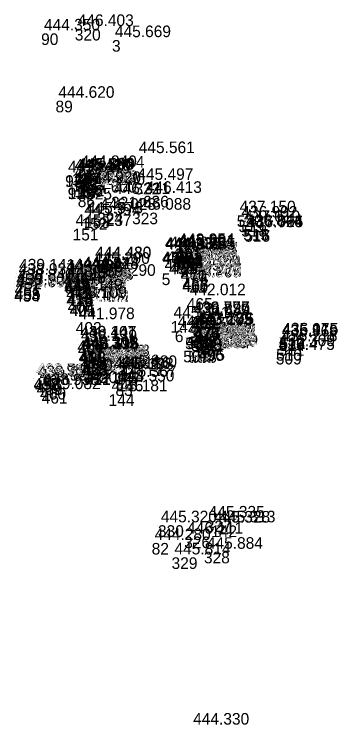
# Model space of a CAD drawing. Extents: x -874038 to -859694, y -1059487 to -1049069.
# Drawn here: x -862371.8 to -862338.4, y -1055776.5 to -1055703.1 of the extents above; entities that cross this region are included whole.
import ezdxf

# ---------------------------------------------------------------- set-up
doc = ezdxf.new("R2010")
doc.units = 0
doc.layers.add('Vrstva 60', color=7, linetype='Continuous')
doc.layers.add('Vrstva 61', color=7, linetype='Continuous')

msp = doc.modelspace()

# ---------------------------------------------------------------- linework, layer by layer
at = {"layer": 'Vrstva 60'}
for p, q in [((-862365.565, -1055704.586), (-862365.565, -1055704.586)), ((-862369.05, -1055705.05), (-862369.05, -1055705.05)), ((-862361.717, -1055705.74), (-862361.717, -1055705.74)), ((-862367.56, -1055712.01), (-862367.56, -1055712.01)), ((-862359.25, -1055717.731), (-862359.25, -1055717.731)), ((-862365.591, -1055719.458), (-862365.591, -1055719.458)), ((-862365.45, -1055719.42), (-862365.45, -1055719.42)), ((-862365.25, -1055719.17), (-862365.25, -1055719.17)), ((-862366.56, -1055719.71), (-862366.56, -1055719.71)), ((-862366.56, -1055719.71), (-862366.56, -1055719.71)), ((-862365.866, -1055719.528), (-862365.866, -1055719.528)), ((-862365.85, -1055720.2), (-862365.85, -1055720.2)), ((-862365.606, -1055719.806), (-862365.606, -1055719.806)), ((-862365.591, -1055720.806), (-862365.591, -1055720.806)), ((-862365.314, -1055720.738), (-862365.314, -1055720.738)), ((-862365.16, -1055720.7), (-862365.16, -1055720.7)), ((-862364.81, -1055720.82), (-862364.81, -1055720.82)), ((-862359.397, -1055720.499), (-862359.397, -1055720.499)), ((-862366.3, -1055720.98), (-862366.3, -1055720.98)), ((-862366.3, -1055720.98), (-862366.3, -1055720.98)), ((-862364.394, -1055721.02), (-862364.394, -1055721.02)), ((-862365.26, -1055721.81), (-862365.26, -1055721.81)), ((-862361.809, -1055721.938), (-862361.809, -1055721.938)), ((-862358.517, -1055721.836), (-862358.517, -1055721.836)), ((-862363.256, -1055723.589), (-862363.256, -1055723.589)), ((-862359.637, -1055723.577), (-862359.637, -1055723.577)), ((-862348.811, -1055723.848), (-862348.811, -1055723.848)), ((-862364.872, -1055724.147), (-862364.872, -1055724.147)), ((-862364.617, -1055723.963), (-862364.617, -1055723.963)), ((-862348.627, -1055724.394), (-862348.627, -1055724.394)), ((-862365.792, -1055725.249), (-862365.792, -1055725.249)), ((-862348.344, -1055724.851), (-862348.344, -1055724.851)), ((-862348.138, -1055725.26), (-862348.138, -1055725.26)), ((-862348.026, -1055725.384), (-862348.026, -1055725.384)), ((-862348.024, -1055725.378), (-862348.024, -1055725.378)), ((-862356.066, -1055727.562), (-862356.066, -1055727.562)), ((-862355.138, -1055727.234), (-862355.138, -1055727.234)), ((-862355.089, -1055727.351), (-862355.089, -1055727.351)), ((-862356.549, -1055727.623), (-862356.549, -1055727.623)), ((-862356.467, -1055727.707), (-862356.467, -1055727.707)), ((-862355.414, -1055728.269), (-862355.414, -1055728.269)), ((-862355.406, -1055728.269), (-862355.406, -1055728.269)), ((-862355.035, -1055727.706), (-862355.035, -1055727.706)), ((-862354.939, -1055727.94), (-862354.939, -1055727.94)), ((-862354.925, -1055728.107), (-862354.925, -1055728.107)), ((-862354.908, -1055728.109), (-862354.908, -1055728.109)), ((-862354.813, -1055728.102), (-862354.813, -1055728.102)), ((-862354.808, -1055728.11), (-862354.808, -1055728.11)), ((-862363.76, -1055728.61), (-862363.76, -1055728.61)), ((-862363.74, -1055728.59), (-862363.74, -1055728.59)), ((-862355.806, -1055728.753), (-862355.806, -1055728.753)), ((-862355.547, -1055728.726), (-862355.547, -1055728.726)), ((-862355.304, -1055728.669), (-862355.304, -1055728.669)), ((-862354.775, -1055728.842), (-862354.775, -1055728.842)), ((-862365.035, -1055729.692), (-862365.035, -1055729.692)), ((-862365.021, -1055729.644), (-862365.021, -1055729.644)), ((-862363.901, -1055729.174), (-862363.901, -1055729.174)), ((-862354.625, -1055729.36), (-862354.625, -1055729.36)), ((-862354.595, -1055729.484), (-862354.595, -1055729.484)), ((-862354.58, -1055729.478), (-862354.58, -1055729.478)), ((-862354.527, -1055729.419), (-862354.527, -1055729.419)), ((-862371.67, -1055730.304), (-862371.67, -1055730.304)), ((-862371.625, -1055729.855), (-862371.625, -1055729.855)), ((-862366.755, -1055729.997), (-862366.755, -1055729.997)), ((-862366.708, -1055729.98), (-862366.708, -1055729.98)), ((-862366.636, -1055730.512), (-862366.636, -1055730.512)), ((-862366.615, -1055730.364), (-862366.615, -1055730.364)), ((-862365.927, -1055729.834), (-862365.927, -1055729.834)), ((-862363.294, -1055730.413), (-862363.294, -1055730.413)), ((-862356.571, -1055729.865), (-862356.571, -1055729.865)), ((-862354.401, -1055730.321), (-862354.401, -1055730.321)), ((-862371.796, -1055730.913), (-862371.796, -1055730.913)), ((-862366.645, -1055730.767), (-862366.645, -1055730.767)), ((-862366.644, -1055730.769), (-862366.644, -1055730.769)), ((-862366.579, -1055730.755), (-862366.579, -1055730.755)), ((-862366.573, -1055730.751), (-862366.573, -1055730.751)), ((-862366.435, -1055730.72), (-862366.435, -1055730.72)), ((-862366.059, -1055730.665), (-862366.059, -1055730.665)), ((-862366.058, -1055730.652), (-862366.058, -1055730.652)), ((-862365.984, -1055730.975), (-862365.984, -1055730.975)), ((-862365.794, -1055730.924), (-862365.794, -1055730.924)), ((-862365.57, -1055730.83), (-862365.57, -1055730.83)), ((-862354.446, -1055730.572), (-862354.446, -1055730.572)), ((-862354.388, -1055730.545), (-862354.388, -1055730.545)), ((-862371.835, -1055731.526), (-862371.835, -1055731.526)), ((-862371.822, -1055731.584), (-862371.822, -1055731.584)), ((-862371.777, -1055731.333), (-862371.777, -1055731.333)), ((-862366.435, -1055731.371), (-862366.435, -1055731.371)), ((-862366.335, -1055731.82), (-862366.335, -1055731.82)), ((-862366.44, -1055732.016), (-862366.44, -1055732.016)), ((-862366.309, -1055732.034), (-862366.309, -1055732.034)), ((-862366.303, -1055732.034), (-862366.303, -1055732.034)), ((-862366.29, -1055732.697), (-862366.29, -1055732.697)), ((-862353.977, -1055732.419), (-862353.977, -1055732.419)), ((-862366.114, -1055733.077), (-862366.114, -1055733.077)), ((-862366.063, -1055733.077), (-862366.063, -1055733.077)), ((-862365.468, -1055734.89), (-862365.468, -1055734.89)), ((-862355.647, -1055734.79), (-862355.647, -1055734.79)), ((-862353.603, -1055734.258), (-862353.603, -1055734.258)), ((-862353.57, -1055734.258), (-862353.57, -1055734.258)), ((-862353.519, -1055734.482), (-862353.519, -1055734.482)), ((-862353.295, -1055735.38), (-862353.295, -1055735.38)), ((-862353.265, -1055735.386), (-862353.265, -1055735.386)), ((-862353.236, -1055735.492), (-862353.236, -1055735.492)), ((-862353.111, -1055735.42), (-862353.111, -1055735.42)), ((-862355.213, -1055735.757), (-862355.213, -1055735.757)), ((-862353.64, -1055736.35), (-862353.64, -1055736.35)), ((-862353.102, -1055736.031), (-862353.102, -1055736.031)), ((-862365.3, -1055736.808), (-862365.3, -1055736.808)), ((-862365.279, -1055736.785), (-862365.279, -1055736.785)), ((-862354.154, -1055736.496), (-862354.154, -1055736.496)), ((-862353.913, -1055736.424), (-862353.913, -1055736.424)), ((-862353.55, -1055736.693), (-862353.55, -1055736.693)), ((-862353.55, -1055736.698), (-862353.55, -1055736.698)), ((-862353.05, -1055736.593), (-862353.05, -1055736.593)), ((-862352.994, -1055736.583), (-862352.994, -1055736.583)), ((-862352.965, -1055736.573), (-862352.965, -1055736.573)), ((-862352.932, -1055736.569), (-862352.932, -1055736.569)), ((-862352.915, -1055737.116), (-862352.915, -1055737.116)), ((-862352.909, -1055737.015), (-862352.909, -1055737.015)), ((-862344.444, -1055736.681), (-862344.444, -1055736.681)), ((-862344.417, -1055736.498), (-862344.417, -1055736.498)), ((-862344.385, -1055736.469), (-862344.385, -1055736.469)), ((-862365.228, -1055737.157), (-862365.228, -1055737.157)), ((-862354.346, -1055737.851), (-862354.346, -1055737.851)), ((-862352.821, -1055737.707), (-862352.821, -1055737.707)), ((-862352.709, -1055737.649), (-862352.709, -1055737.649)), ((-862344.742, -1055737.681), (-862344.742, -1055737.681)), ((-862344.488, -1055737.174), (-862344.488, -1055737.174)), ((-862365.18, -1055737.938), (-862365.18, -1055737.938)), ((-862365.077, -1055737.876), (-862365.077, -1055737.876)), ((-862365.074, -1055737.876), (-862365.074, -1055737.876)), ((-862365.024, -1055738.013), (-862365.024, -1055738.013)), ((-862364.928, -1055738.52), (-862364.928, -1055738.52)), ((-862353.833, -1055737.891), (-862353.833, -1055737.891)), ((-862353.554, -1055737.898), (-862353.554, -1055737.898)), ((-862344.761, -1055738.068), (-862344.761, -1055738.068)), ((-862364.854, -1055739.179), (-862364.854, -1055739.179)), ((-862364.853, -1055739.201), (-862364.853, -1055739.201)), ((-862364.775, -1055739.172), (-862364.775, -1055739.172)), ((-862364.764, -1055739.188), (-862364.764, -1055739.188)), ((-862364.67, -1055739.123), (-862364.67, -1055739.123)), ((-862364.335, -1055738.742), (-862364.335, -1055738.742)), ((-862364.286, -1055739.065), (-862364.286, -1055739.065)), ((-862364.275, -1055739.065), (-862364.275, -1055739.065)), ((-862364.154, -1055738.714), (-862364.154, -1055738.714)), ((-862363.914, -1055738.715), (-862363.914, -1055738.715)), ((-862364.706, -1055739.469), (-862364.706, -1055739.469)), ((-862364.659, -1055739.617), (-862364.659, -1055739.617)), ((-862363.864, -1055739.974), (-862363.864, -1055739.974)), ((-862362.95, -1055739.753), (-862362.95, -1055739.753)), ((-862362.948, -1055739.753), (-862362.948, -1055739.753)), ((-862361.787, -1055740.014), (-862361.787, -1055740.014)), ((-862361.08, -1055739.836), (-862361.08, -1055739.836)), ((-862369.832, -1055740.726), (-862369.832, -1055740.726)), ((-862369.824, -1055740.678), (-862369.824, -1055740.678)), ((-862364.526, -1055740.151), (-862364.526, -1055740.151)), ((-862364.511, -1055740.188), (-862364.511, -1055740.188)), ((-862361.425, -1055740.082), (-862361.425, -1055740.082)), ((-862369.697, -1055740.9), (-862369.697, -1055740.9)), ((-862369.512, -1055741.235), (-862369.512, -1055741.235)), ((-862361.36, -1055741.32), (-862361.36, -1055741.32)), ((-862361.154, -1055740.851), (-862361.154, -1055740.851)), ((-862369.154, -1055741.697), (-862369.154, -1055741.697)), ((-862368.991, -1055742.119), (-862368.991, -1055742.119)), ((-862362.067, -1055742.349), (-862362.067, -1055742.349)), ((-862352.013, -1055755.394), (-862352.013, -1055755.394)), ((-862356.961, -1055755.89), (-862356.961, -1055755.89)), ((-862351.451, -1055755.916), (-862351.451, -1055755.916)), ((-862350.903, -1055755.892), (-862350.903, -1055755.892)), ((-862354.245, -1055757.062), (-862354.245, -1055757.062)), ((-862357.61, -1055757.72), (-862357.61, -1055757.72)), ((-862352.201, -1055758.627), (-862352.201, -1055758.627)), ((-862355.552, -1055759.207), (-862355.552, -1055759.207))]:
    msp.add_line(p, q, dxfattribs=at)

# ---------------------------------------------------------------- texts
for s, p in [('320', (-862365.565, -1055705.786)), ('90', (-862369.05, -1055706.25)), ('3', (-862361.717, -1055706.94)), ('89', (-862367.56, -1055713.21)), ('4', (-862359.25, -1055718.931)), ('187', (-862365.591, -1055720.658)), ('131', (-862365.45, -1055720.62)), ('88', (-862365.25, -1055720.37)), ('92', (-862366.56, -1055720.91)), ('134', (-862366.56, -1055720.91)), ('185', (-862365.866, -1055720.728)), ('135', (-862365.85, -1055721.4)), ('637', (-862365.606, -1055721.006)), ('91', (-862366.3, -1055722.18)), ('133', (-862366.3, -1055722.18)), ('184', (-862365.591, -1055722.006)), ('186', (-862365.314, -1055721.938)), ('132', (-862365.16, -1055721.9)), ('87', (-862364.81, -1055722.02)), ('322', (-862359.397, -1055721.699)), ('325', (-862364.394, -1055722.22)), ('86', (-862365.26, -1055723.01)), ('321', (-862361.809, -1055723.138)), ('636', (-862358.517, -1055723.036)), ('324', (-862363.256, -1055724.789)), ('323', (-862359.637, -1055724.777)), ('520', (-862348.811, -1055725.048)), ('152', (-862364.872, -1055725.347)), ('153', (-862364.617, -1055725.163)), ('519', (-862348.627, -1055725.594)), ('151', (-862365.792, -1055726.449)), ('518', (-862348.344, -1055726.051)), ('515', (-862348.138, -1055726.46)), ('516', (-862348.026, -1055726.584)), ('517', (-862348.024, -1055726.578)), ('480', (-862356.066, -1055728.762)), ('481', (-862355.138, -1055728.434)), ('491', (-862355.089, -1055728.551)), ('479', (-862356.549, -1055728.823)), ('478', (-862356.467, -1055728.907)), ('487', (-862355.414, -1055729.469)), ('486', (-862355.406, -1055729.469)), ('482', (-862355.035, -1055728.906)), ('492', (-862354.939, -1055729.14)), ('483', (-862354.925, -1055729.307)), ('524', (-862354.908, -1055729.309)), ('484', (-862354.813, -1055729.302)), ('485', (-862354.808, -1055729.31)), ('85', (-862363.76, -1055729.81)), ('84', (-862363.74, -1055729.79)), ('490', (-862355.806, -1055729.953)), ('489', (-862355.547, -1055729.926)), ('488', (-862355.304, -1055729.869)), ('473', (-862354.775, -1055730.042)), ('448', (-862365.035, -1055730.892)), ('449', (-862365.021, -1055730.844)), ('150', (-862363.901, -1055730.374)), ('469', (-862354.625, -1055730.56)), ('470', (-862354.595, -1055730.684)), ('471', (-862354.58, -1055730.678)), ('472', (-862354.527, -1055730.619)), ('452', (-862371.67, -1055731.504)), ('450', (-862371.625, -1055731.055)), ('444', (-862366.755, -1055731.197)), ('445', (-862366.708, -1055731.18)), ('443', (-862366.636, -1055731.712)), ('446', (-862366.615, -1055731.564)), ('447', (-862365.927, -1055731.034)), ('149', (-862363.294, -1055731.613)), ('5', (-862356.571, -1055731.065)), ('468', (-862354.401, -1055731.521)), ('451', (-862371.796, -1055732.113)), ('441', (-862366.645, -1055731.967)), ('442', (-862366.644, -1055731.969)), ('440', (-862366.573, -1055731.951)), ('521', (-862366.579, -1055731.955)), ('434', (-862366.435, -1055731.92)), ('438', (-862366.059, -1055731.865)), ('439', (-862366.058, -1055731.852)), ('437', (-862365.984, -1055732.175)), ('436', (-862365.794, -1055732.124)), ('435', (-862365.57, -1055732.03)), ('466', (-862354.446, -1055731.772)), ('467', (-862354.388, -1055731.745)), ('453', (-862371.835, -1055732.726)), ('454', (-862371.822, -1055732.784)), ('455', (-862371.777, -1055732.533)), ('417', (-862366.435, -1055732.571)), ('413', (-862366.335, -1055733.02)), ('416', (-862366.44, -1055733.216)), ('415', (-862366.309, -1055733.234)), ('414', (-862366.303, -1055733.234)), ('406', (-862366.29, -1055733.897)), ('465', (-862353.977, -1055733.619)), ('405', (-862366.114, -1055734.277)), ('401', (-862366.063, -1055734.277)), ('402', (-862365.468, -1055736.09)), ('143', (-862355.647, -1055735.99)), ('464', (-862353.603, -1055735.458)), ('463', (-862353.57, -1055735.458)), ('462', (-862353.519, -1055735.682)), ('476', (-862353.295, -1055736.58)), ('475', (-862353.265, -1055736.586)), ('474', (-862353.236, -1055736.692)), ('477', (-862353.111, -1055736.62)), ('6', (-862355.213, -1055736.957)), ('503', (-862353.64, -1055737.55)), ('493', (-862353.102, -1055737.231)), ('404', (-862365.3, -1055738.008)), ('403', (-862365.279, -1055737.985)), ('505', (-862354.154, -1055737.696)), ('504', (-862353.913, -1055737.624)), ('502', (-862353.55, -1055737.893)), ('501', (-862353.55, -1055737.898)), ('498', (-862353.05, -1055737.793)), ('523', (-862352.994, -1055737.783)), ('500', (-862352.965, -1055737.773)), ('499', (-862352.932, -1055737.769)), ('497', (-862352.915, -1055738.316)), ('494', (-862352.909, -1055738.215)), ('514', (-862344.444, -1055737.881)), ('513', (-862344.417, -1055737.698)), ('512', (-862344.385, -1055737.669)), ('407', (-862365.228, -1055738.357)), ('410', (-862365.077, -1055739.076)), ('409', (-862365.074, -1055739.076)), ('507', (-862354.346, -1055739.051)), ('496', (-862352.821, -1055738.907)), ('495', (-862352.709, -1055738.849)), ('510', (-862344.742, -1055738.881)), ('511', (-862344.488, -1055738.374)), ('411', (-862365.18, -1055739.138)), ('408', (-862365.024, -1055739.213)), ('412', (-862364.928, -1055739.72)), ('506', (-862353.833, -1055739.091)), ('508', (-862353.554, -1055739.098)), ('509', (-862344.761, -1055739.268)), ('425', (-862364.854, -1055740.379)), ('424', (-862364.853, -1055740.401)), ('423', (-862364.764, -1055740.388)), ('522', (-862364.775, -1055740.372)), ('431', (-862364.67, -1055740.323)), ('430', (-862364.335, -1055739.942)), ('426', (-862364.286, -1055740.265)), ('427', (-862364.275, -1055740.265)), ('429', (-862364.154, -1055739.914)), ('428', (-862363.914, -1055739.915)), ('433', (-862364.706, -1055740.669)), ('422', (-862364.659, -1055740.817)), ('420', (-862363.864, -1055741.174)), ('418', (-862362.95, -1055740.953)), ('419', (-862362.948, -1055740.953)), ('145', (-862361.787, -1055741.214)), ('148', (-862361.08, -1055741.036)), ('458', (-862369.832, -1055741.926)), ('457', (-862369.824, -1055741.878)), ('432', (-862364.526, -1055741.351)), ('421', (-862364.511, -1055741.388)), ('147', (-862361.425, -1055741.282)), ('456', (-862369.697, -1055742.1)), ('459', (-862369.512, -1055742.435)), ('83', (-862361.36, -1055742.52)), ('146', (-862361.154, -1055742.051)), ('460', (-862369.154, -1055742.897)), ('461', (-862368.991, -1055743.319)), ('144', (-862362.067, -1055743.549)), ('327', (-862352.013, -1055756.594)), ('330', (-862356.961, -1055757.09)), ('142', (-862351.451, -1055757.116)), ('7', (-862350.903, -1055757.092)), ('326', (-862354.245, -1055758.262)), ('82', (-862357.61, -1055758.92)), ('328', (-862352.201, -1055759.827)), ('329', (-862355.552, -1055760.407))]:
    msp.add_text(s, height=1.2, dxfattribs=at).set_placement(p)
at = {"layer": 'Vrstva 61'}
for s, p in [('446.403', (-862365.265, -1055704.286)), ('444.350', (-862368.75, -1055704.75)), ('445.669', (-862361.417, -1055705.44)), ('444.620', (-862367.26, -1055711.71)), ('445.561', (-862358.95, -1055717.431)), ('445.420', (-862365.566, -1055719.228)), ('445.590', (-862365.291, -1055719.158)), ('445.800', (-862365.15, -1055719.12)), ('444.840', (-862364.95, -1055718.87)), ('445.810', (-862366.26, -1055719.41)), ('445.210', (-862366.26, -1055719.41)), ('445.810', (-862365.55, -1055719.9)), ('446.407', (-862365.306, -1055719.506)), ('445.800', (-862366, -1055720.68)), ('445.200', (-862366, -1055720.68)), ('445.413', (-862365.291, -1055720.506)), ('445.585', (-862365.014, -1055720.438)), ('445.810', (-862364.86, -1055720.4)), ('444.920', (-862364.51, -1055720.52)), ('445.497', (-862359.097, -1055720.199)), ('445.670', (-862364.094, -1055720.72)), ('444.600', (-862364.96, -1055721.51)), ('446.311', (-862361.509, -1055721.638)), ('446.413', (-862358.217, -1055721.536)), ('446.028', (-862362.956, -1055723.289)), ('446.088', (-862359.337, -1055723.277)), ('437.150', (-862348.511, -1055723.548)), ('445.394', (-862364.572, -1055723.847)), ('445.573', (-862364.317, -1055723.663)), ('436.992', (-862348.327, -1055724.094)), ('445.237', (-862365.492, -1055724.949)), ('437.010', (-862348.044, -1055724.551)), ('436.844', (-862347.838, -1055724.96)), ('436.765', (-862347.726, -1055725.084)), ('437.024', (-862347.724, -1055725.078)), ('444.235', (-862356.249, -1055727.323)), ('444.025', (-862355.766, -1055727.262)), ('443.854', (-862354.838, -1055726.934)), ('443.001', (-862354.789, -1055727.051)), ('444.839', (-862356.167, -1055727.407)), ('444.033', (-862355.114, -1055727.969)), ('444.208', (-862355.106, -1055727.969)), ('443.855', (-862354.735, -1055727.406)), ('443.024', (-862354.639, -1055727.64)), ('443.946', (-862354.625, -1055727.807)), ('443.070', (-862354.608, -1055727.809)), ('443.987', (-862354.513, -1055727.802)), ('444.212', (-862354.508, -1055727.81)), ('444.430', (-862363.46, -1055728.31)), ('444.480', (-862363.44, -1055728.29)), ('444.186', (-862355.506, -1055728.453)), ('444.129', (-862355.247, -1055728.426)), ('444.195', (-862355.004, -1055728.369)), ('443.308', (-862354.475, -1055728.542)), ('444.828', (-862364.735, -1055729.392)), ('444.444', (-862364.721, -1055729.344)), ('445.290', (-862363.601, -1055728.874)), ('443.122', (-862354.325, -1055729.06)), ('443.142', (-862354.295, -1055729.184)), ('443.343', (-862354.28, -1055729.178)), ('443.300', (-862354.227, -1055729.119)), ('438.937', (-862371.37, -1055730.004)), ('439.141', (-862371.325, -1055729.555)), ('443.022', (-862366.455, -1055729.697)), ('443.936', (-862366.408, -1055729.68)), ('443.059', (-862366.336, -1055730.212)), ('443.876', (-862366.315, -1055730.064)), ('444.037', (-862365.627, -1055729.534)), ('445.290', (-862362.994, -1055730.113)), ('445.435', (-862356.271, -1055729.565)), ('436.967', (-862354.101, -1055730.021)), ('436.978', (-862354.088, -1055730.245)), ('438.840', (-862371.496, -1055730.613)), ('443.935', (-862366.345, -1055730.467)), ('444.165', (-862366.344, -1055730.469)), ('443.131', (-862366.279, -1055730.455)), ('443.952', (-862366.273, -1055730.451)), ('445.273', (-862366.135, -1055730.42)), ('444.149', (-862365.759, -1055730.365)), ('443.953', (-862365.758, -1055730.352)), ('444.109', (-862365.684, -1055730.675)), ('444.079', (-862365.494, -1055730.624)), ('444.115', (-862365.27, -1055730.53)), ('439.809', (-862354.146, -1055730.272)), ('438.794', (-862371.535, -1055731.226)), ('438.600', (-862371.522, -1055731.284)), ('438.602', (-862371.477, -1055731.033)), ('443.300', (-862366.14, -1055731.716)), ('443.313', (-862366.135, -1055731.071)), ('443.236', (-862366.035, -1055731.52)), ('443.332', (-862366.009, -1055731.734)), ('443.236', (-862366.003, -1055731.734)), ('438.109', (-862365.99, -1055732.397)), ('442.012', (-862353.677, -1055732.119)), ('438.029', (-862365.814, -1055732.777)), ('440.102', (-862365.763, -1055732.777)), ('441.978', (-862365.168, -1055734.59)), ('445.441', (-862355.347, -1055734.49)), ('439.776', (-862353.303, -1055733.958)), ('436.897', (-862353.27, -1055733.958)), ('436.889', (-862353.219, -1055734.182)), ('443.282', (-862352.995, -1055735.08)), ('443.175', (-862352.965, -1055735.086)), ('443.105', (-862352.936, -1055735.192)), ('443.276', (-862352.811, -1055735.12)), ('445.435', (-862354.913, -1055735.457)), ('444.134', (-862353.613, -1055736.124)), ('444.197', (-862353.34, -1055736.05)), ('443.251', (-862352.802, -1055735.731)), ('438.107', (-862365, -1055736.508)), ('440.441', (-862364.979, -1055736.485)), ('438.139', (-862364.928, -1055736.857)), ('444.178', (-862353.854, -1055736.196)), ('443.960', (-862353.25, -1055736.393)), ('444.241', (-862353.25, -1055736.398)), ('443.940', (-862352.75, -1055736.293)), ('443.046', (-862352.694, -1055736.283)), ('444.240', (-862352.665, -1055736.273)), ('444.007', (-862352.632, -1055736.269)), ('443.805', (-862352.615, -1055736.816)), ('442.885', (-862352.609, -1055736.715)), ('435.969', (-862344.144, -1055736.381)), ('435.975', (-862344.117, -1055736.198)), ('436.115', (-862344.085, -1055736.169)), ('443.316', (-862364.777, -1055737.576)), ('443.212', (-862364.774, -1055737.576)), ('444.881', (-862354.046, -1055737.551)), ('443.946', (-862353.533, -1055737.591)), ('443.654', (-862353.254, -1055737.598)), ('443.896', (-862352.521, -1055737.407)), ('442.899', (-862352.409, -1055737.349)), ('436.309', (-862344.442, -1055737.381)), ('436.218', (-862344.188, -1055736.874)), ('443.305', (-862364.88, -1055737.638)), ('443.196', (-862364.724, -1055737.713)), ('443.316', (-862364.628, -1055738.22)), ('436.475', (-862344.461, -1055737.768)), ('444.153', (-862364.554, -1055738.879)), ('443.888', (-862364.553, -1055738.901)), ('443.014', (-862364.475, -1055738.872)), ('443.886', (-862364.464, -1055738.888)), ('445.268', (-862364.37, -1055738.823)), ('444.103', (-862364.035, -1055738.442)), ('444.137', (-862363.986, -1055738.765)), ('443.946', (-862363.975, -1055738.765)), ('444.064', (-862363.854, -1055738.414)), ('444.108', (-862363.614, -1055738.415)), ('442.877', (-862364.406, -1055739.169)), ('443.846', (-862364.359, -1055739.317)), ('443.969', (-862363.564, -1055739.674)), ('444.774', (-862362.65, -1055739.453)), ('444.451', (-862362.648, -1055739.453)), ('445.136', (-862361.487, -1055739.714)), ('445.198', (-862361.125, -1055739.782)), ('445.480', (-862360.78, -1055739.536)), ('438.954', (-862369.532, -1055740.426)), ('438.714', (-862369.524, -1055740.378)), ('442.991', (-862364.226, -1055739.851)), ('443.873', (-862364.211, -1055739.888)), ('438.719', (-862369.397, -1055740.6)), ('438.903', (-862369.212, -1055740.935)), ('444.550', (-862361.06, -1055741.02)), ('445.367', (-862360.854, -1055740.551)), ('438.935', (-862368.854, -1055741.397)), ('439.082', (-862368.691, -1055741.819)), ('445.181', (-862361.767, -1055742.049)), ('445.335', (-862351.713, -1055755.094)), ('445.320', (-862356.661, -1055755.59)), ('445.328', (-862351.151, -1055755.616)), ('445.313', (-862350.603, -1055755.592)), ('444.280', (-862357.31, -1055757.42)), ('446.111', (-862353.945, -1055756.762)), ('445.814', (-862355.252, -1055758.907)), ('445.884', (-862351.901, -1055758.327)), ('444.330', (-862353.32, -1055776.5))]:
    msp.add_text(s, height=1.2, dxfattribs=at).set_placement(p)

doc.saveas('drawing.dxf')
